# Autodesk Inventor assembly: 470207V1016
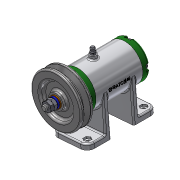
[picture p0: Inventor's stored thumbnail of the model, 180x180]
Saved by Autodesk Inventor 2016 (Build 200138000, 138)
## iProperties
Created: 2017-02
Part Number: 470207V1016
Material: 일반
Document SubType Name: Assembly
Designer: H
Author: H
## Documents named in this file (16)
- C:\Users\CAMTIC\Desktop\470207V1016\답안조립품.iam
- C:\Users\CAMTIC\Desktop\470207V1016\본체.ipt
- C:\Users\CAMTIC\Desktop\470207V1016\V벨트풀리.ipt
- C:\Users\CAMTIC\Desktop\470207V1016\너트 M 8.ipt
- C:\Users\CAMTIC\Desktop\470207V1016\니플 M 6 x 0.75.ipt
- C:\Users\CAMTIC\Desktop\470207V1016\뒤커버.ipt
- C:\Users\CAMTIC\Desktop\470207V1016\베어링 15 x 32 x 9.ipt
- C:\Users\CAMTIC\Desktop\470207V1016\볼트 M 6 x 8.ipt
- C:\Users\CAMTIC\Desktop\470207V1016\볼트 M4 x 12.ipt
- C:\Users\CAMTIC\Desktop\470207V1016\스프링와셔 8.ipt
- C:\Users\CAMTIC\Desktop\470207V1016\앞커버.ipt
- C:\Users\CAMTIC\Desktop\470207V1016\오일 실 15 25 7.ipt
- C:\Users\CAMTIC\Desktop\470207V1016\와셔 6x11.5.ipt
- C:\Users\CAMTIC\Desktop\470207V1016\와셔 8x17.ipt
- C:\Users\CAMTIC\Desktop\470207V1016\축.ipt
- C:\Users\CAMTIC\Desktop\470207V1016\키 3 x 3 x 12.ipt
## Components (11 placed, 3 different names)
1. V벨트풀리:1
2. KS B 2023 6002 - 15 x 32 x 9:1
3. KS B 2023 6002 - 15 x 32 x 9:2
4. ISO 4762 M4 x 12:1
5. ISO 4762 M4 x 12:3
6. ISO 4762 M4 x 12:4
7. ISO 4762 M4 x 12:5
8. ISO 4762 M4 x 12:2
9. ISO 4762 M4 x 12:6
10. ISO 4762 M4 x 12:7
11. ISO 4762 M4 x 12:8
